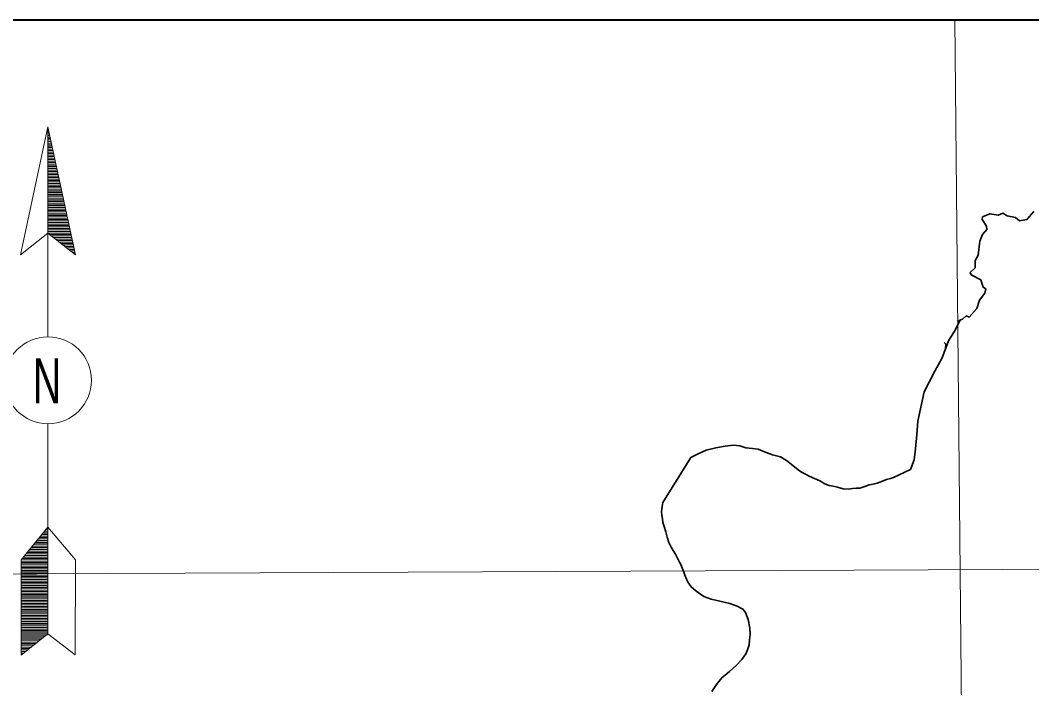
# Model space of a CAD drawing. Extents: x -10.5 to 30.8, y 18.4 to 58.7.
# Drawn here: x -1.4 to 5.3, y 54.32 to 58.74 of the extents above; entities that cross this region are included whole.
import ezdxf

# ---------------------------------------------------------------- set-up
doc = ezdxf.new("R2010")
doc.units = 0
doc.header["$LTSCALE"] = 0.08
doc.linetypes.add('DASH_DOUBLE_DOT', pattern=[9.2, 5, -1.2, 0.3, -1.2, 0.3, -1.2])
for name, color, linetype, lineweight in [('20', 7, 'DASH_DOUBLE_DOT', 35), ('29', 7, 'Continuous', 13), ('52', 7, 'Continuous', 13), ('57', 7, 'DASH_DOUBLE_DOT', 25), ('60', 7, 'Continuous', 13)]:
    doc.layers.add(name, color=color, linetype=linetype, lineweight=lineweight)

msp = doc.modelspace()

# ---------------------------------------------------------------- linework, layer by layer
at = {"layer": '20'}
for points in [[(4.80919, 56.75155), (4.8421, 56.76488), (4.86548, 56.78602), (4.88518, 56.77687), (4.93502, 56.83501), (4.95384, 56.88948), (4.988, 56.9376), (4.9954, 56.96558), (4.97755, 56.97688), (4.96183, 57.02502), (4.89807, 57.05888), (4.89102, 57.07427), (4.92614, 57.1054), (4.92614, 57.15346), (4.94429, 57.18768), (4.95628, 57.28147), (4.97412, 57.32526), (5.00309, 57.35847), (5.00093, 57.38082), (4.97197, 57.42359), (4.97324, 57.44226), (5.02156, 57.4617), (5.07698, 57.45283), (5.10928, 57.46754), (5.1373, 57.44822), (5.1915, 57.43701), (5.21886, 57.41547), (5.26785, 57.42472), (5.31309, 57.47794)], [(4.82564, 56.75822), (4.78777, 56.68618), (4.74751, 56.62176), (4.70725, 56.50901), (4.65894, 56.42043), (4.58647, 56.28353), (4.54621, 56.09026), (4.53816, 56.00168), (4.53011, 55.90505), (4.52205, 55.83257), (4.4979, 55.76815), (4.38399, 55.71519)], [(3.17751, 54.91131), (3.12954, 54.92799), (3.08384, 54.95973), (3.0482, 54.98913), (3.02767, 55.0163), (3.01466, 55.04359), (3.00421, 55.06842), (2.99634, 55.0883), (2.98843, 55.11068), (2.97799, 55.13552), (2.96762, 55.15535), (2.95721, 55.17769), (2.94165, 55.20744), (2.92617, 55.23219), (2.91325, 55.25449), (2.89764, 55.28673), (2.88702, 55.32158), (2.8764, 55.35642), (2.86578, 55.39126), (2.85779, 55.41864), (2.85487, 55.4436), (2.85203, 55.46357), (2.84906, 55.49103), (2.85353, 55.52363), (2.85809, 55.55123), (3.04388, 55.84965), (3.09118, 55.87298), (3.1435, 55.8964), (3.20849, 55.91253), (3.27106, 55.92362), (3.32368, 55.92954), (3.36642, 55.92527), (3.40678, 55.91346), (3.45203, 55.90923), (3.48975, 55.90488), (3.53023, 55.88557), (3.58327, 55.86647), (3.63621, 55.85237), (3.67678, 55.82806), (3.71747, 55.79624), (3.75311, 55.76684), (3.77594, 55.75222), (3.80129, 55.73765), (3.82659, 55.72558), (3.86202, 55.70868), (3.8974, 55.69428), (3.93035, 55.67483), (3.95816, 55.66281), (3.98584, 55.65828), (4.01357, 55.65125), (4.05139, 55.6419), (4.08656, 55.64001), (4.11412, 55.64298), (4.13666, 55.64587), (4.16176, 55.64631), (4.19421, 55.65688), (4.22416, 55.6674), (4.24917, 55.67283), (4.27668, 55.67832), (4.3116, 55.69143), (4.33904, 55.70191), (4.36402, 55.70984), (4.38399, 55.71519)], [(3.18274, 54.29848), (3.21204, 54.34652), (3.24899, 54.38968), (3.2985, 54.43057), (3.343, 54.47137), (3.37997, 54.51203), (3.40699, 54.54752), (3.41908, 54.57525), (3.42858, 54.60794), (3.43054, 54.64049), (3.43497, 54.6756), (3.43426, 54.71811), (3.42326, 54.77546), (3.40491, 54.82267), (3.38697, 54.84488), (3.34899, 54.86424), (3.30101, 54.88092), (3.23548, 54.8973), (3.17751, 54.91131)]]:
    msp.add_lwpolyline(points, dxfattribs=at)
at = {"layer": '29', "linetype": 'DASH_DOUBLE_DOT', "lineweight": 35}
for points in [[(4.80919, 56.75155), (4.8421, 56.76488), (4.86548, 56.78602), (4.88518, 56.77687), (4.93502, 56.83501), (4.95384, 56.88948), (4.988, 56.9376), (4.9954, 56.96558), (4.97755, 56.97688), (4.96183, 57.02502), (4.89807, 57.05888), (4.89102, 57.07427), (4.92614, 57.1054), (4.92614, 57.15346), (4.94429, 57.18768), (4.95628, 57.28147), (4.97412, 57.32526), (5.00309, 57.35847), (5.00093, 57.38082), (4.97197, 57.42359), (4.97324, 57.44226), (5.02156, 57.4617), (5.07698, 57.45283), (5.10928, 57.46754), (5.1373, 57.44822), (5.1915, 57.43701), (5.21886, 57.41547), (5.26785, 57.42472), (5.31309, 57.47794)], [(4.82564, 56.75822), (4.78777, 56.68618), (4.74751, 56.62176), (4.70725, 56.50901), (4.65894, 56.42043), (4.58647, 56.28353), (4.54621, 56.09026), (4.53816, 56.00168), (4.53011, 55.90505), (4.52205, 55.83257), (4.4979, 55.76815), (4.38399, 55.71519)], [(3.17751, 54.91131), (3.12954, 54.92799), (3.08384, 54.95973), (3.0482, 54.98913), (3.02767, 55.0163), (3.01466, 55.04359), (3.00421, 55.06842), (2.99634, 55.0883), (2.98843, 55.11068), (2.97799, 55.13552), (2.96762, 55.15535), (2.95721, 55.17769), (2.94165, 55.20744), (2.92617, 55.23219), (2.91325, 55.25449), (2.89764, 55.28673), (2.88702, 55.32158), (2.8764, 55.35642), (2.86578, 55.39126), (2.85779, 55.41864), (2.85487, 55.4436), (2.85203, 55.46357), (2.84906, 55.49103), (2.85353, 55.52363), (2.85809, 55.55123), (3.04388, 55.84965), (3.09118, 55.87298), (3.1435, 55.8964), (3.20849, 55.91253), (3.27106, 55.92362), (3.32368, 55.92954), (3.36642, 55.92527), (3.40678, 55.91346), (3.45203, 55.90923), (3.48975, 55.90488), (3.53023, 55.88557), (3.58327, 55.86647), (3.63621, 55.85237), (3.67678, 55.82806), (3.71747, 55.79624), (3.75311, 55.76684), (3.77594, 55.75222), (3.80129, 55.73765), (3.82659, 55.72558), (3.86202, 55.70868), (3.8974, 55.69428), (3.93035, 55.67483), (3.95816, 55.66281), (3.98584, 55.65828), (4.01357, 55.65125), (4.05139, 55.6419), (4.08656, 55.64001), (4.11412, 55.64298), (4.13666, 55.64587), (4.16176, 55.64631), (4.19421, 55.65688), (4.22416, 55.6674), (4.24917, 55.67283), (4.27668, 55.67832), (4.3116, 55.69143), (4.33904, 55.70191), (4.36402, 55.70984), (4.38399, 55.71519)], [(3.18274, 54.29848), (3.21204, 54.34652), (3.24899, 54.38968), (3.2985, 54.43057), (3.343, 54.47137), (3.37997, 54.51203), (3.40699, 54.54752), (3.41908, 54.57525), (3.42858, 54.60794), (3.43054, 54.64049), (3.43497, 54.6756), (3.43426, 54.71811), (3.42326, 54.77546), (3.40491, 54.82267), (3.38697, 54.84488), (3.34899, 54.86424), (3.30101, 54.88092), (3.23548, 54.8973), (3.17751, 54.91131)]]:
    msp.add_lwpolyline(points, dxfattribs=at)
at = {"layer": '29'}
for points in [[(5.31309, 57.47794), (5.26785, 57.42472), (5.21886, 57.41547), (5.1915, 57.43701), (5.1373, 57.44822), (5.10928, 57.46754), (5.07698, 57.45283), (5.02156, 57.4617), (4.97324, 57.44226), (4.97197, 57.42359), (5.00093, 57.38082), (5.00309, 57.35847), (4.97412, 57.32526), (4.95628, 57.28147), (4.94429, 57.18768), (4.92614, 57.15346), (4.92614, 57.1054), (4.89102, 57.07427), (4.89807, 57.05888), (4.96183, 57.02502), (4.97755, 56.97688), (4.9954, 56.96558), (4.988, 56.9376), (4.95384, 56.88948), (4.93502, 56.83501), (4.88518, 56.77687), (4.86548, 56.78602), (4.8421, 56.76488), (4.82564, 56.75822)], [(4.82564, 56.75822), (4.78777, 56.68618), (4.74751, 56.62176), (4.70725, 56.50901), (4.65894, 56.42043), (4.58647, 56.28353), (4.54621, 56.09026), (4.53816, 56.00168), (4.53011, 55.90505), (4.52205, 55.83257), (4.4979, 55.76815), (4.38399, 55.71519)], [(4.38399, 55.71519), (4.36402, 55.70984), (4.33904, 55.70191), (4.3116, 55.69143), (4.27668, 55.67832), (4.24917, 55.67283), (4.22416, 55.6674), (4.19421, 55.65688), (4.16176, 55.64631), (4.13666, 55.64587), (4.11412, 55.64298), (4.08656, 55.64001), (4.05139, 55.6419), (4.01357, 55.65125), (3.98584, 55.65828), (3.95816, 55.66281), (3.93035, 55.67483), (3.8974, 55.69428), (3.86202, 55.70868), (3.82659, 55.72558), (3.80129, 55.73765), (3.77594, 55.75222), (3.75311, 55.76684), (3.71747, 55.79624), (3.67678, 55.82806), (3.63621, 55.85237), (3.58327, 55.86647), (3.53023, 55.88557), (3.48975, 55.90488), (3.45203, 55.90923), (3.40678, 55.91346), (3.36642, 55.92527), (3.32368, 55.92954), (3.27106, 55.92362), (3.20849, 55.91253), (3.1435, 55.8964), (3.09118, 55.87298), (3.04388, 55.84965), (2.85809, 55.55123), (2.85353, 55.52363), (2.84906, 55.49103), (2.85203, 55.46357), (2.85487, 55.4436), (2.85779, 55.41864), (2.86578, 55.39126), (2.8764, 55.35642), (2.88702, 55.32158), (2.89764, 55.28673), (2.91325, 55.25449), (2.92617, 55.23219), (2.94165, 55.20744), (2.95721, 55.17769), (2.96762, 55.15535), (2.97799, 55.13552), (2.98843, 55.11068), (2.99634, 55.0883), (3.00421, 55.06842), (3.01466, 55.04359), (3.02767, 55.0163), (3.0482, 54.98913), (3.08384, 54.95973), (3.12954, 54.92799), (3.17751, 54.91131)], [(3.17751, 54.91131), (3.23548, 54.8973), (3.30101, 54.88092), (3.34899, 54.86424), (3.38697, 54.84488), (3.40491, 54.82267), (3.42326, 54.77546), (3.43426, 54.71811), (3.43497, 54.6756), (3.43054, 54.64049), (3.42858, 54.60794), (3.41908, 54.57525), (3.40699, 54.54752), (3.37997, 54.51203), (3.343, 54.47137), (3.2985, 54.43057), (3.24899, 54.38968), (3.21204, 54.34652), (3.18274, 54.29848)]]:
    msp.add_lwpolyline(points, dxfattribs=at)
at = {"layer": '52'}
for points in [[(4.79009, 58.74412), (4.82513, 55.08853), (4.87817, 49.55368), (4.93123, 44.01892), (4.98428, 38.48381), (5.03734, 32.94795), (5.09042, 27.4109), (5.14008, 22.22857)], [(-9.64995, 55.04028), (10.02308, 55.12986), (15.22114, 55.15419), (20.41926, 55.16152), (25.61737, 55.15186), (29.72684, 55.13079)]]:
    msp.add_lwpolyline(points, dxfattribs=at)
at = {"layer": '57'}
msp.add_lwpolyline([(4.719, 56.55117), (4.72974, 56.56754), (4.73068, 56.5981), (4.719, 56.60914)], dxfattribs=at)
at = {"layer": '60', "lineweight": 40}
msp.add_line((30.75566, 58.74412), (-10.13304, 58.74412), dxfattribs=at)
at = {"layer": '60'}
for p, q in [((-1.21234, 56.6495), (-1.21234, 58.03909)), ((-1.21234, 58.02952), (-1.21043, 58.02952)), ((-1.21234, 58.01995), (-1.20851, 58.01995)), ((-1.21234, 58.00847), (-1.20468, 58.00847)), ((-1.21234, 57.9989), (-1.20468, 57.9989)), ((-1.21234, 57.98933), (-1.20277, 57.98933)), ((-1.21234, 57.98167), (-1.19894, 57.98167)), ((-1.21234, 57.97019), (-1.19703, 57.97019)), ((-1.21234, 57.96062), (-1.19511, 57.96062)), ((-1.21234, 57.95105), (-1.1932, 57.95105)), ((-1.21234, 57.94148), (-1.19129, 57.94148)), ((-1.21234, 57.92999), (-1.18937, 57.92999)), ((-1.21234, 57.91851), (-1.18937, 57.91851)), ((-1.21234, 57.91085), (-1.18363, 57.91085)), ((-1.21234, 57.90128), (-1.18172, 57.90128)), ((-1.21234, 57.8898), (-1.1798, 57.8898)), ((-1.21234, 57.88214), (-1.17789, 57.88214)), ((-1.21234, 57.87066), (-1.17597, 57.87066)), ((-1.21234, 57.86109), (-1.17406, 57.86109)), ((-1.21234, 57.8496), (-1.17215, 57.8496)), ((-1.21234, 57.84195), (-1.17023, 57.84195)), ((-1.21234, 57.83046), (-1.1664, 57.83046)), ((-1.21234, 57.82089), (-1.1664, 57.82089)), ((-1.21234, 57.81132), (-1.16449, 57.81132)), ((-1.21234, 57.80175), (-1.16257, 57.80175)), ((-1.21234, 57.79027), (-1.15875, 57.79027)), ((-1.21234, 57.7807), (-1.15683, 57.7807)), ((-1.21234, 57.77304), (-1.153, 57.77304)), ((-1.21234, 57.76156), (-1.153, 57.76156)), ((-1.21234, 57.75199), (-1.15109, 57.75199)), ((-1.21234, 57.74242), (-1.14918, 57.74242)), ((-1.21234, 57.73093), (-1.14535, 57.73093)), ((-1.21234, 57.72328), (-1.14535, 57.72328)), ((-1.21234, 57.71179), (-1.14343, 57.71179)), ((-1.21234, 57.70222), (-1.13961, 57.70222)), ((-1.21234, 57.69265), (-1.13769, 57.69265)), ((-1.21234, 57.68308), (-1.13578, 57.68308)), ((-1.21234, 57.67351), (-1.13386, 57.67351)), ((-1.21234, 57.66203), (-1.13195, 57.66203)), ((-1.21234, 57.65246), (-1.13004, 57.65246)), ((-1.21234, 57.64289), (-1.12621, 57.64289)), ((-1.21234, 57.63332), (-1.12429, 57.63332)), ((-1.21234, 57.62183), (-1.12238, 57.62183)), ((-1.21234, 57.61226), (-1.12238, 57.61226)), ((-1.21234, 57.60269), (-1.11855, 57.60269)), ((-1.21234, 57.59312), (-1.11664, 57.59312)), ((-1.21234, 57.58547), (-1.11281, 57.58547)), ((-1.21234, 57.57398), (-1.11281, 57.57398)), ((-1.21234, 57.5625), (-1.10898, 57.5625)), ((-1.21234, 57.55293), (-1.10898, 57.55293)), ((-1.21234, 57.54336), (-1.10515, 57.54336)), ((-1.21234, 57.53379), (-1.10324, 57.53379)), ((-1.21234, 57.5223), (-1.10324, 57.5223)), ((-1.21234, 57.51465), (-1.09941, 57.51465)), ((-1.21234, 57.50508), (-1.0975, 57.50508)), ((-1.21234, 57.49359), (-1.09558, 57.49359)), ((-1.21234, 57.48402), (-1.09367, 57.48402)), ((-1.21234, 57.47445), (-1.08984, 57.47445)), ((-1.21234, 57.46297), (-1.08984, 57.46297)), ((-1.21234, 57.4534), (-1.08601, 57.4534)), ((-1.21234, 57.44574), (-1.08601, 57.44574)), ((-1.21234, 57.43426), (-1.08218, 57.43426)), ((-1.21234, 57.42469), (-1.08218, 57.42469)), ((-1.21234, 57.41512), (-1.07836, 57.41512)), ((-1.21234, 57.40554), (-1.07644, 57.40554)), ((-1.21234, 57.39406), (-1.07453, 57.39406)), ((-1.21234, 57.38449), (-1.07261, 57.38449)), ((-1.21234, 57.37492), (-1.0707, 57.37492)), ((-1.21234, 57.36535), (-1.06879, 57.36535)), ((-1.21234, 57.35578), (-1.06496, 57.35578)), ((-1.21234, 57.34621), (-1.06304, 57.34621)), ((-1.21234, 57.33473), (-1.06113, 57.33473)), ((-1.20277, 57.32515), (-1.05922, 57.32515)), ((-1.18937, 57.31558), (-1.0573, 57.31558)), ((-1.17597, 57.30601), (-1.05539, 57.30601)), ((-1.16449, 57.29453), (-1.05539, 57.29453)), ((-1.15109, 57.28496), (-1.05156, 57.28496)), ((-1.13769, 57.27539), (-1.04965, 57.27539)), ((-1.12621, 57.26582), (-1.04582, 57.26582)), ((-1.11281, 57.25625), (-1.0439, 57.25625)), ((-1.10133, 57.24668), (-1.04199, 57.24668)), ((-1.08601, 57.23711), (-1.04008, 57.23711)), ((-1.07644, 57.22562), (-1.03816, 57.22562)), ((-1.06304, 57.21605), (-1.03625, 57.21605)), ((-1.05156, 57.20648), (-1.03242, 57.20648)), ((-1.03816, 57.195), (-1.03051, 57.195)), ((-1.21234, 54.68186), (-1.21234, 56.07146)), ((-1.21808, 55.37857), (-1.21234, 55.37857)), ((-1.2755, 55.30967), (-1.21234, 55.30967)), ((-1.26593, 55.31924), (-1.21234, 55.31924)), ((-1.25828, 55.32881), (-1.21234, 55.32881)), ((-1.25062, 55.33838), (-1.21234, 55.33838)), ((-1.24296, 55.34795), (-1.21234, 55.34795)), ((-1.23339, 55.35752), (-1.21234, 55.35752)), ((-1.22574, 55.369), (-1.21234, 55.369)), ((-1.33292, 55.23885), (-1.21234, 55.23885)), ((-1.32527, 55.25033), (-1.21234, 55.25033)), ((-1.3157, 55.25799), (-1.21234, 55.25799)), ((-1.30996, 55.26947), (-1.21234, 55.26947)), ((-1.30039, 55.28095), (-1.21234, 55.28095)), ((-1.29273, 55.28861), (-1.21234, 55.28861)), ((-1.28316, 55.29818), (-1.21234, 55.29818)), ((-1.38269, 55.17951), (-1.21234, 55.17951)), ((-1.37312, 55.18908), (-1.21234, 55.18908)), ((-1.36546, 55.20056), (-1.21234, 55.20056)), ((-1.35781, 55.21013), (-1.21234, 55.21013)), ((-1.35015, 55.21971), (-1.21234, 55.21971)), ((-1.34058, 55.22928), (-1.21234, 55.22928)), ((-1.39035, 55.16994), (-1.21234, 55.16994)), ((-1.39035, 55.15846), (-1.21234, 55.15846)), ((-1.39035, 55.1508), (-1.21234, 55.1508)), ((-1.39035, 55.14123), (-1.21234, 55.14123)), ((-1.39035, 55.12974), (-1.21234, 55.12974)), ((-1.39035, 55.12017), (-1.21234, 55.12017)), ((-1.39035, 55.1106), (-1.21234, 55.1106)), ((-1.39035, 55.10103), (-1.21234, 55.10103)), ((-1.39035, 55.09146), (-1.21234, 55.09146)), ((-1.39035, 55.08189), (-1.21234, 55.08189)), ((-1.39035, 55.07041), (-1.21234, 55.07041)), ((-1.39035, 55.06084), (-1.21234, 55.06084)), ((-1.39035, 55.05127), (-1.21234, 55.05127)), ((-1.39035, 55.0417), (-1.21234, 55.0417)), ((-1.39035, 55.03021), (-1.21234, 55.03021)), ((-1.39035, 55.02064), (-1.21234, 55.02064)), ((-1.39035, 55.01299), (-1.21234, 55.01299)), ((-1.39035, 55.0015), (-1.21234, 55.0015)), ((-1.39035, 54.99002), (-1.21234, 54.99002)), ((-1.39035, 54.98236), (-1.21234, 54.98236)), ((-1.39035, 54.97088), (-1.21234, 54.97088)), ((-1.39035, 54.96131), (-1.21234, 54.96131)), ((-1.39035, 54.94982), (-1.21234, 54.94982)), ((-1.39035, 54.94217), (-1.21234, 54.94217)), ((-1.39035, 54.9326), (-1.21234, 54.9326)), ((-1.39035, 54.92303), (-1.21234, 54.92303)), ((-1.39035, 54.91346), (-1.21234, 54.91346)), ((-1.39035, 54.90197), (-1.21234, 54.90197)), ((-1.39035, 54.8924), (-1.21234, 54.8924)), ((-1.39035, 54.88283), (-1.21234, 54.88283)), ((-1.39035, 54.87326), (-1.21234, 54.87326)), ((-1.39035, 54.86178), (-1.21234, 54.86178)), ((-1.39035, 54.85412), (-1.21234, 54.85412)), ((-1.39035, 54.84264), (-1.21234, 54.84264)), ((-1.39035, 54.83307), (-1.21234, 54.83307)), ((-1.39035, 54.8235), (-1.21234, 54.8235)), ((-1.39035, 54.81393), (-1.21234, 54.81393)), ((-1.39035, 54.80244), (-1.21234, 54.80244)), ((-1.39035, 54.79287), (-1.21234, 54.79287)), ((-1.39035, 54.7833), (-1.21234, 54.7833)), ((-1.39035, 54.77373), (-1.21234, 54.77373)), ((-1.39035, 54.76225), (-1.21234, 54.76225)), ((-1.39035, 54.75268), (-1.21234, 54.75268)), ((-1.39035, 54.74502), (-1.21234, 54.74502)), ((-1.39035, 54.73354), (-1.21234, 54.73354)), ((-1.39035, 54.72205), (-1.21234, 54.72205)), ((-1.39035, 54.71248), (-1.21234, 54.71248)), ((-1.39035, 54.70291), (-1.21234, 54.70291)), ((-1.39035, 54.69526), (-1.21234, 54.69526)), ((-1.39035, 54.68569), (-1.21234, 54.68569)), ((-1.39035, 54.6742), (-1.21617, 54.6742)), ((-1.39035, 54.66463), (-1.22957, 54.66463)), ((-1.39035, 54.65506), (-1.24296, 54.65506)), ((-1.39035, 54.64549), (-1.25636, 54.64549)), ((-1.39035, 54.63401), (-1.26976, 54.63401)), ((-1.39035, 54.62252), (-1.28316, 54.62252)), ((-1.39035, 54.61487), (-1.29273, 54.61487)), ((-1.39035, 54.6053), (-1.30804, 54.6053)), ((-1.39035, 54.59381), (-1.31953, 54.59381)), ((-1.39035, 54.58424), (-1.33292, 54.58424)), ((-1.39035, 54.57467), (-1.34632, 54.57467)), ((-1.39035, 54.5651), (-1.35781, 54.5651)), ((-1.39035, 54.55362), (-1.37312, 54.55362)), ((-1.39035, 54.54596), (-1.3846, 54.54596))]:
    msp.add_line(p, q, dxfattribs=at)
for points in [[(-1.21234, 58.03909), (-1.39417, 57.19117), (-1.21234, 57.33473)], [(-1.21234, 58.03909), (-1.03051, 57.19117), (-1.21234, 57.33473)], [(-1.21234, 55.38623), (-1.39035, 55.16994), (-1.39035, 54.54022), (-1.21234, 54.67994)], [(-1.21234, 55.38623), (-1.03051, 55.16994), (-1.03242, 54.54213), (-1.21234, 54.68186)]]:
    msp.add_lwpolyline(points, close=True, dxfattribs=at)
msp.add_circle((-1.21176, 56.35999), 0.28791, dxfattribs=at)

# ---------------------------------------------------------------- texts
at = {"layer": '60', "width": 0.65}
msp.add_text('N', height=0.2976, dxfattribs=at).set_placement((-1.31186, 56.20736))

doc.saveas('drawing.dxf')
